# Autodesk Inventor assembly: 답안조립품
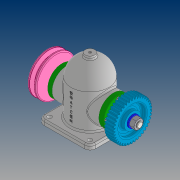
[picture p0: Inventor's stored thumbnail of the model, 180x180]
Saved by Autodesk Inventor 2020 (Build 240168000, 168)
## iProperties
Created: 2021-08
Part Number: 답안조립품
Document SubType Name: Assembly
Designer: PC312-
Author: PC312-
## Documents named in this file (14)
- C:\Users\PC312-\OneDrive - 경남대학교 산학협력단\바탕 화면\710809V1011\답안조립품.iam
- C:\Users\PC312-\OneDrive - 경남대학교 산학협력단\바탕 화면\710809V1011\본체.ipt
- C:\Users\PC312-\OneDrive - 경남대학교 산학협력단\바탕 화면\710809V1011\커버.ipt
- C:\Users\PC312-\OneDrive - 경남대학교 산학협력단\바탕 화면\710809V1011\축.ipt
- C:\Users\PC312-\OneDrive - 경남대학교 산학협력단\바탕 화면\710809V1011\키 5x5x12.ipt
- C:\Users\PC312-\OneDrive - 경남대학교 산학협력단\바탕 화면\710809V1011\베어링 6203.ipt
- C:\Users\PC312-\OneDrive - 경남대학교 산학협력단\바탕 화면\710809V1011\부시.ipt
- C:\Users\PC312-\OneDrive - 경남대학교 산학협력단\바탕 화면\710809V1011\V-벨트풀리.ipt
- V-벨트풀리.ipt
- C:\Users\PC312-\OneDrive - 경남대학교 산학협력단\바탕 화면\710809V1011\스퍼기어.ipt
- C:\Users\PC312-\OneDrive - 경남대학교 산학협력단\바탕 화면\710809V1011\와셔 12x24.ipt
- C:\Users\PC312-\OneDrive - 경남대학교 산학협력단\바탕 화면\710809V1011\너트 M12x1.25.ipt
- C:\Users\PC312-\OneDrive - 경남대학교 산학협력단\바탕 화면\710809V1011\볼트 M4.ipt
- C:\Users\PC312-\OneDrive - 경남대학교 산학협력단\바탕 화면\710809V1011\오일 실 26 38 8.ipt
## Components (1 placed, 1 different names)
1. V-벨트풀리:1
